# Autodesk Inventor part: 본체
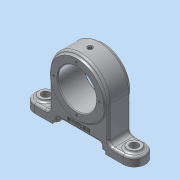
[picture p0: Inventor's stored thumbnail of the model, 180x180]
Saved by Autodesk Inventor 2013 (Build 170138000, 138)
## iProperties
Created: 2019-05
Part Number: 본체
Material: 알루미늄 6061
Document SubType Name: Modeling
Designer: dgall
Density: 2.71 g/cm^3
Mass: 458.157 g
Surface Area: 320.595 cm^2
Volume: 169.062 cm^3
Author: dgall
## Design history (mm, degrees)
sketch "스케치2"
  geometry: L1 (-75, 15)-(75, 15); L2 (75, 15)-(75, -15); L3 (75, -15)-(-75, -15); L4 (-75, -15)-(-75, 15); 3 further points
  constraints: 8 end point, 2 midpoint, 2 parallel, 1 horizontal, 1 horizontal alignment, 1 perpendicular, 1 vertical alignment
  dimensions: "d0" = 150 distance of L1.start L1.end; "d2" = 30 distance of L3.end L1.start
extrude "돌출1" new body sketch "스케치2" distance "d3" = 12; taper "d4" = 0 deg
sketch "스케치3"
  geometry: L1 (-75, 0)-(75, 0) reference; L2 (75, 0)-(-75, 0) reference; C1 r 40 at (0, 60); C2 r 36 at (0, 60); C3 r 26 at (0, 60); C4 r 1.5 at (0, 86); 3 further points
  constraints: 4 centre point, 2 coincident, 2 midpoint, 2 vertical alignment
  dimensions: "d15" = 80 diameter of C1; "d16" = 72 diameter of C2; "d17" = 52 diameter of C3; "d18" = 60 distance from line of C3.centre L1; "d73" = 3 diameter of C4; "d74" = 26 distance of C1.centre C4.centre
extrude "돌출2" join sketch "스케치3" stored distance "d19" = 30; taper "d20" = 0 deg
extrude "돌출3" join sketch "스케치3" stored distance "d21" = 36; taper "d22" = 0 deg
sketch "스케치5"
  geometry: L1 (-40, 15)-(40, 15); L2 (40, 15)-(40, -15); L3 (40, -15)-(-40, -15); L4 (-40, -15)-(-40, 15); L5 (-75, 15)-(75, 15) reference; 4 further points
  constraints: 8 end point, 4 midpoint, 2 parallel, 1 horizontal, 1 horizontal alignment, 1 perpendicular, 1 vertical alignment
  dimensions: "d23" = 80 distance of L1.start L1.end
extrude "돌출4" join sketch "스케치5" stored distance "d26" = 36; taper "d27" = 0 deg
sketch "스케치6"
  geometry: L1 (39, 10)-(111, 10); L2 (111, 10)-(111, 0); L3 (111, 0)-(39, 0); L4 (39, 0)-(39, 10); L5 (39, 4)-(45, 4); L6 (45, 4)-(45, 10); L7 (105, 10)-(105, 4); L8 (105, 4)-(111, 4); L9 (150, 0)-(0, 0) reference; A1 r 40 centre (75, 60) between (115, 60) and (35, 60) reference; 3 further points
  constraints: 16 end point, 4 perpendicular, 4 point on line, 3 parallel, 2 equal length, 2 midpoint, 1 coincident, 1 collinear, 1 horizontal
  dimensions: "d28" = 72 distance of L2.end L3.end; "d30" = 60 distance between parallel lines of L7 L6; "d31" = 4 distance between parallel lines of L3 L5; "d32" = 10 distance of L1.end L2.end
extrude "돌출5" cut sketch "스케치6" stored distance "d33" = 36; taper "d34" = 0 deg
fillet "모깎기1" dims "d37" = 15
sketch "스케치9"
  geometry: C1 r 9 at (-60, 0); C2 r 5.5 at (-60, 0); 1 further point
  constraints: 2 centre point, 1 coincident
  dimensions: "d38" = 18 diameter of C1; "d39" = 11 diameter of C2; "d40" = 60 distance of C2.centre point (0, 0)
extrude "돌출6" join sketch "스케치9" distance "d41" = 3; taper "d42" = 0 deg
extrude "돌출7" cut sketch "스케치9" stored distance "d43" = 3; taper "d44" = 0 deg
sketch "스케치11"
  geometry: C1 r 26 at (0, 0) reference; C2 r 36 at (0, 0) reference; 2 further points
  constraints: 1 vertical alignment
  dimensions: "d53" = 31 distance of point (0, 31) C1.centre
hole "구멍2" sketch "스케치11" at (0, 31) diameter "d54" = 3.242; stored, may be unused: countersink angle "d58" = 90 deg, drill point angle "d60" = 118 deg; dims "d55" = 6, "d56" = 7, "d57" = 1, "d59" = 8
fillet "모깎기2" dims "d64" = 6
fillet "모깎기3" dims "d65" = 3
fillet "모깎기5" dims "d67" = 3
fillet "모깎기6" dims "d68" = 3
fillet "모깎기7" dims "d69" = 3
fillet "모깎기9" dims "d71" = 3
fillet "모깎기10" dims "d72" = 3
extrude "돌출8" cut sketch "스케치3" stored distance "d75" = 3; taper "d76" = 0 deg
node "작업 평면2"
sketch "스케치12"
  geometry: L1 (-27, 10)-(27, 10) reference; 2 further points
  constraints: 1 vertical alignment, 1 other
  dimensions: "d85" = 7 distance from line of point (0, 17) L1
feature "엠보싱1" sketch "스케치12" dims "d86" = 0.5, "d87" = 0
fillet "모깎기11" dims "d88" = 3
chamfer "모따기1" distance "d89" = 1; stored, may be unused: second distance "d90" = 2, angle "d91" = 45 deg
node "작업 평면4"
node "작업 평면5"
node "작업 평면6"
sketch "스케치17"
  geometry: 2 further points
  constraints: 1 coincident
hole "구멍6" sketch "스케치17" at (0, 0) diameter "d118" = 4.917; stored, may be unused: countersink angle "d122" = 82 deg, drill point angle "d124" = 118 deg; dims "d119" = 8, "d120" = 7, "d121" = 1, "d123" = 10
node "작업 평면7"
sketch "스케치18"
  geometry: 1 further point
sketch "스케치19"
  geometry: L1 (0, -30.683)-(1, -30.683); L2 (1, -30.683)-(1, -25.981); L3 (1, -25.981)-(0, -25.981); L4 (0, -25.981)-(0, -30.683); L5 (-2.458, -30)-(2.458, -30) reference; A1 r 26 centre (0, 0) between (1.499, -25.957) and (-1.499, -25.957) reference; 1 further point
  constraints: 8 end point, 2 parallel, 1 horizontal, 1 perpendicular, 1 point on circle, 1 vertical alignment
  dimensions: "d125" = 2 diameter of L2 L4
revolve "회전2" sketch "스케치19" stored, may be unused: angle "d127" = 90 deg
node "솔리드1"
mirror "대칭1"
pattern_circular "원형 패턴1" dims angle "d62" = 360 deg
mirror "대칭2"
node "투영된 루프1"
other parameters: "d84" = -61.25
